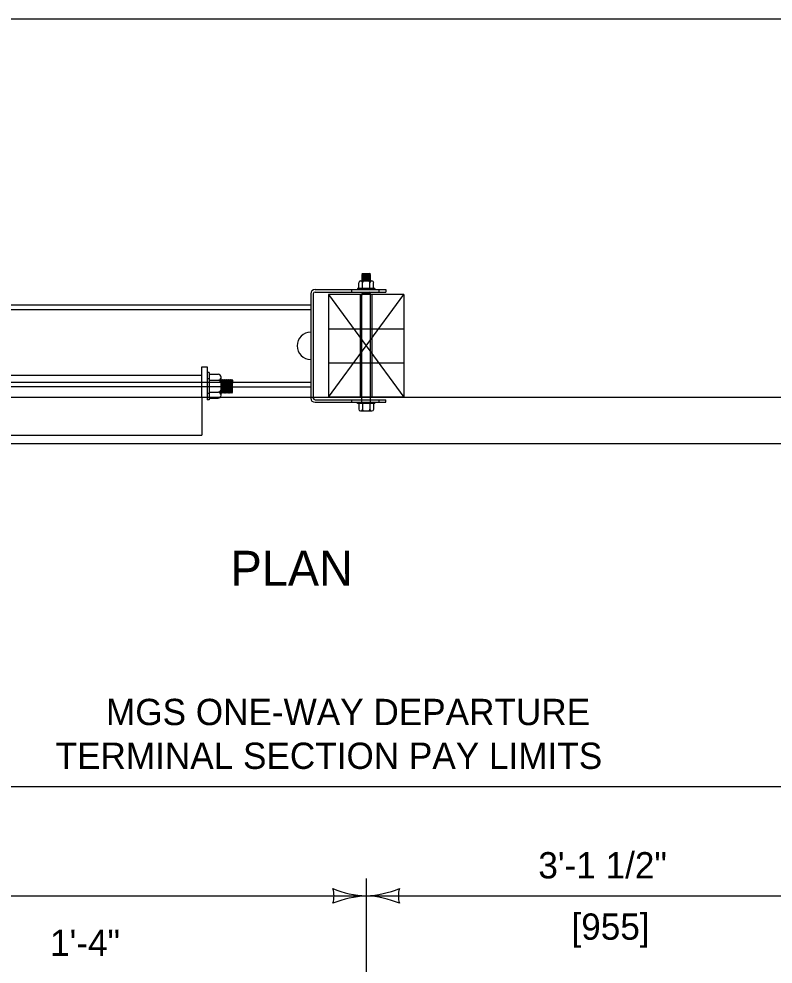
# Model space of a CAD drawing. Extents: x 49991.4 to 50021, y 49987.6 to 50011.4.
# Drawn here: x 50002.896 to 50004.618, y 49996.841 to 49998.999 of the extents above; entities that cross this region are included whole.
import ezdxf

# ---------------------------------------------------------------- set-up
doc = ezdxf.new("R2010")
doc.units = 0
for name, color, linetype in [('Level 1', 7, 'Continuous'), ('Level 2', 7, 'Continuous'), ('Level 3', 7, 'Continuous'), ('Level 4', 7, 'Continuous')]:
    doc.layers.add(name, color=color, linetype=linetype)

msp = doc.modelspace()

# ---------------------------------------------------------------- linework, layer by layer
at = {"layer": 'Level 1'}
for p, q in [((50003.6976, 49998.4176), (50003.6792, 49998.4166)), ((50003.6792, 49998.4166), (50003.6805, 49998.4176)), ((50003.6792, 49998.4166), (50003.6805, 49998.4156)), ((50003.6976, 49998.4156), (50003.6792, 49998.4147)), ((50003.6792, 49998.4147), (50003.6805, 49998.4156)), ((50003.6792, 49998.4147), (50003.6805, 49998.4137)), ((50003.6976, 49998.4137), (50003.6792, 49998.4128)), ((50003.6792, 49998.4128), (50003.6805, 49998.4137)), ((50003.6792, 49998.4128), (50003.6805, 49998.4118)), ((50003.6976, 49998.4118), (50003.6792, 49998.4109)), ((50003.6792, 49998.4109), (50003.6805, 49998.4118)), ((50003.6792, 49998.4109), (50003.6805, 49998.4099)), ((50003.6805, 49998.4176), (50003.6976, 49998.4176)), ((50003.6987, 49998.4166), (50003.6805, 49998.4156)), ((50003.6987, 49998.4147), (50003.6805, 49998.4137)), ((50003.6987, 49998.4128), (50003.6805, 49998.4118)), ((50003.6987, 49998.4109), (50003.6805, 49998.4099)), ((50003.6976, 49998.4176), (50003.6987, 49998.4166)), ((50003.6976, 49998.4156), (50003.6987, 49998.4166)), ((50003.6976, 49998.4156), (50003.6987, 49998.4147)), ((50003.6976, 49998.4137), (50003.6987, 49998.4147)), ((50003.6976, 49998.4137), (50003.6987, 49998.4128)), ((50003.6976, 49998.4118), (50003.6987, 49998.4128)), ((50003.6976, 49998.4118), (50003.6987, 49998.4109)), ((50003.6976, 49998.4099), (50003.6987, 49998.4109)), ((50003.672, 49998.384), (50003.672, 49998.3969)), ((50003.6762, 49998.401), (50003.7018, 49998.401)), ((50003.6976, 49998.4099), (50003.6792, 49998.409)), ((50003.6792, 49998.409), (50003.6805, 49998.4099)), ((50003.6792, 49998.409), (50003.6805, 49998.408)), ((50003.6976, 49998.408), (50003.6792, 49998.407)), ((50003.6792, 49998.407), (50003.6805, 49998.408)), ((50003.6792, 49998.407), (50003.6805, 49998.406)), ((50003.6976, 49998.406), (50003.6792, 49998.4051)), ((50003.6792, 49998.4051), (50003.6805, 49998.406)), ((50003.6792, 49998.4051), (50003.6805, 49998.4042)), ((50003.6976, 49998.4042), (50003.6792, 49998.4032)), ((50003.6792, 49998.4032), (50003.6805, 49998.4042)), ((50003.6792, 49998.4032), (50003.6805, 49998.4022)), ((50003.6976, 49998.4022), (50003.6792, 49998.4013)), ((50003.6792, 49998.4013), (50003.6805, 49998.4022)), ((50003.6792, 49998.4013), (50003.6796, 49998.401)), ((50003.6987, 49998.409), (50003.6805, 49998.408)), ((50003.6987, 49998.407), (50003.6805, 49998.406)), ((50003.6987, 49998.4051), (50003.6805, 49998.4042)), ((50003.6987, 49998.4032), (50003.6805, 49998.4022)), ((50003.6805, 49998.384), (50003.6805, 49998.3969)), ((50003.6987, 49998.4013), (50003.6956, 49998.401)), ((50003.6975, 49998.384), (50003.6975, 49998.3969)), ((50003.6976, 49998.4099), (50003.6987, 49998.409)), ((50003.6976, 49998.408), (50003.6987, 49998.409)), ((50003.6976, 49998.408), (50003.6987, 49998.407)), ((50003.6976, 49998.406), (50003.6987, 49998.407)), ((50003.6976, 49998.406), (50003.6987, 49998.4051)), ((50003.6976, 49998.4042), (50003.6987, 49998.4051)), ((50003.6976, 49998.4042), (50003.6987, 49998.4032)), ((50003.6976, 49998.4022), (50003.6987, 49998.4032)), ((50003.6976, 49998.4022), (50003.6987, 49998.4013)), ((50003.6984, 49998.401), (50003.6987, 49998.4013)), ((50003.706, 49998.384), (50003.706, 49998.3969)), ((50003.5623, 49998.3715), (50003.5623, 49998.1354)), ((50003.5682, 49998.3715), (50003.5682, 49998.1354)), ((50003.5721, 49998.3813), (50003.7339, 49998.3813)), ((50003.5721, 49998.3754), (50003.7339, 49998.3754)), ((50003.6032, 49998.1354), (50003.7748, 49998.3698)), ((50003.6032, 49998.3698), (50003.7748, 49998.1354)), ((50003.6032, 49998.3698), (50003.6032, 49998.1354)), ((50003.7748, 49998.3698), (50003.6032, 49998.3698)), ((50003.7085, 49998.384), (50003.6695, 49998.384)), ((50003.6695, 49998.384), (50003.6695, 49998.3813)), ((50003.6787, 49998.384), (50003.6787, 49998.3813)), ((50003.6976, 49998.3754), (50003.6792, 49998.3745)), ((50003.6792, 49998.3745), (50003.6805, 49998.3754)), ((50003.6792, 49998.3745), (50003.6805, 49998.3735)), ((50003.6976, 49998.3735), (50003.6792, 49998.3726)), ((50003.6792, 49998.3726), (50003.6805, 49998.3735)), ((50003.6792, 49998.3726), (50003.6805, 49998.3716)), ((50003.6976, 49998.3716), (50003.6792, 49998.3707)), ((50003.6792, 49998.3707), (50003.6805, 49998.3716)), ((50003.6792, 49998.3707), (50003.6804, 49998.3698)), ((50003.6805, 49998.3754), (50003.6976, 49998.3754)), ((50003.6987, 49998.3745), (50003.6805, 49998.3735)), ((50003.6987, 49998.3726), (50003.6805, 49998.3716)), ((50003.6987, 49998.3707), (50003.6821, 49998.3698)), ((50003.6976, 49998.3754), (50003.6987, 49998.3745)), ((50003.6976, 49998.3735), (50003.6987, 49998.3745)), ((50003.6976, 49998.3735), (50003.6987, 49998.3726)), ((50003.6976, 49998.3716), (50003.6987, 49998.3726)), ((50003.6976, 49998.3716), (50003.6987, 49998.3707)), ((50003.6977, 49998.3698), (50003.6987, 49998.3707)), ((50003.6994, 49998.384), (50003.6994, 49998.3813)), ((50003.7085, 49998.384), (50003.7085, 49998.3813)), ((50003.7339, 49998.3813), (50003.7339, 49998.3754)), ((50003.7748, 49998.3698), (50003.7748, 49998.1354)), ((50001.4719, 49998.3462), (50003.5623, 49998.3462)), ((50003.5623, 49998.3462), (50003.5623, 49998.2838)), ((50003.5623, 49998.2214), (50003.5623, 49998.159)), ((50003.314, 49998.1354), (50003.314, 49998.205)), ((50003.314, 49998.205), (50003.3257, 49998.205)), ((50003.3257, 49998.205), (50003.3257, 49998.1292)), ((50002.814, 49998.1861), (50003.314, 49998.1861)), ((50003.3301, 49998.1917), (50003.3257, 49998.1917)), ((50003.3301, 49998.1771), (50003.3257, 49998.1771)), ((50003.3301, 49998.1917), (50003.3301, 49998.1292)), ((50003.3301, 49998.1878), (50003.3507, 49998.1878)), ((50003.3301, 49998.1741), (50003.3507, 49998.1741)), ((50003.3574, 49998.1399), (50003.3574, 49998.181)), ((50003.3578, 49998.1761), (50003.3574, 49998.1696)), ((50003.3574, 49998.1756), (50003.3578, 49998.1761)), ((50003.3593, 49998.1741), (50003.3578, 49998.1761)), ((50003.3593, 49998.1741), (50003.3578, 49998.1448)), ((50003.3593, 49998.1741), (50003.3609, 49998.1761)), ((50003.3609, 49998.1761), (50003.3593, 49998.1468)), ((50003.3624, 49998.1741), (50003.3609, 49998.1761)), ((50003.3624, 49998.1741), (50003.3609, 49998.1448)), ((50003.3624, 49998.1741), (50003.364, 49998.1761)), ((50003.364, 49998.1761), (50003.3624, 49998.1468)), ((50003.3655, 49998.1741), (50003.364, 49998.1761)), ((50003.3655, 49998.1741), (50003.364, 49998.1448)), ((50003.3655, 49998.1741), (50003.3671, 49998.1761)), ((50003.3671, 49998.1761), (50003.3655, 49998.1468)), ((50003.3686, 49998.1741), (50003.3671, 49998.1761)), ((50003.3686, 49998.1741), (50003.3671, 49998.1448)), ((50003.3686, 49998.1741), (50003.3701, 49998.1761)), ((50003.3701, 49998.1761), (50003.3686, 49998.1468)), ((50003.3716, 49998.1741), (50003.3701, 49998.1761)), ((50003.3716, 49998.1741), (50003.3701, 49998.1448)), ((50003.3716, 49998.1741), (50003.3732, 49998.1761)), ((50003.3732, 49998.1761), (50003.3716, 49998.1468)), ((50003.3747, 49998.1741), (50003.3732, 49998.1761)), ((50003.3747, 49998.1741), (50003.3732, 49998.1448)), ((50003.3747, 49998.1741), (50003.3763, 49998.1761)), ((50003.3763, 49998.1761), (50003.3747, 49998.1468)), ((50003.3778, 49998.1741), (50003.3763, 49998.1761)), ((50003.3778, 49998.1741), (50003.3763, 49998.1448)), ((50003.3778, 49998.1741), (50003.3794, 49998.1761)), ((50003.3794, 49998.1761), (50003.3778, 49998.1468)), ((50003.3809, 49998.1741), (50003.3794, 49998.1761)), ((50003.3809, 49998.1741), (50003.3794, 49998.1448)), ((50003.3824, 49998.1761), (50003.3809, 49998.1468)), ((50003.3809, 49998.1741), (50003.3824, 49998.1761)), ((50003.3839, 49998.1741), (50003.3824, 49998.1761)), ((50003.3839, 49998.1741), (50003.3824, 49998.1448)), ((50003.3839, 49998.1468), (50003.3839, 49998.1741)), ((50003.3839, 49998.159), (50003.5623, 49998.159)), ((50001.2278, 49998.1354), (50006.4114, 49998.1354)), ((50003.3301, 49998.1438), (50003.3257, 49998.1438)), ((50003.3301, 49998.1468), (50003.3507, 49998.1468)), ((50003.3301, 49998.1331), (50003.3507, 49998.1331)), ((50003.3578, 49998.1448), (50003.3574, 49998.1453)), ((50003.3578, 49998.1448), (50003.3593, 49998.1468)), ((50003.3609, 49998.1448), (50003.3593, 49998.1468)), ((50003.3609, 49998.1448), (50003.3624, 49998.1468)), ((50003.364, 49998.1448), (50003.3624, 49998.1468)), ((50003.364, 49998.1448), (50003.3655, 49998.1468)), ((50003.3671, 49998.1448), (50003.3655, 49998.1468)), ((50003.3671, 49998.1448), (50003.3686, 49998.1468)), ((50003.3701, 49998.1448), (50003.3686, 49998.1468)), ((50003.3701, 49998.1448), (50003.3716, 49998.1468)), ((50003.3732, 49998.1448), (50003.3716, 49998.1468)), ((50003.3732, 49998.1448), (50003.3747, 49998.1468)), ((50003.3763, 49998.1448), (50003.3747, 49998.1468)), ((50003.3763, 49998.1448), (50003.3778, 49998.1468)), ((50003.3794, 49998.1448), (50003.3778, 49998.1468)), ((50003.3794, 49998.1448), (50003.3809, 49998.1468)), ((50003.3824, 49998.1448), (50003.3809, 49998.1468)), ((50003.3824, 49998.1448), (50003.3839, 49998.1468)), ((50003.7748, 49998.1354), (50003.6032, 49998.1354)), ((50003.3301, 49998.1292), (50003.3257, 49998.1292)), ((50001.5093, 49998.0301), (50006.4114, 49998.0301))]:
    msp.add_line(p, q, dxfattribs=at)
msp.add_lwpolyline([(49999.3835, 49998.9992), (50016.7501, 49998.9992), (50016.7501, 49987.7988), (49999.3835, 49987.7988)], close=True, dxfattribs=at)
for centre, radius, start, end in [((50003.6762, 49998.3968), 0.0042, 89.5221, 179.5221), ((50003.6763, 49998.3968), 0.00423, 0.896, 90.896), ((50003.6847, 49998.3968), 0.0042, 92.0518, 179.5951), ((50003.6933, 49998.3969), 0.00418, 0.0618, 87.1409), ((50003.7018, 49998.3968), 0.00426, 88.7945, 178.7945), ((50003.7019, 49998.3969), 0.00418, 0.1602, 90.1602), ((50003.5721, 49998.3715), 0.00975, 90, 180), ((50003.5721, 49998.3715), 0.0039, 90, 180), ((50003.5623, 49998.2526), 0.0312, 90, 270), ((50003.3507, 49998.181), 0.00675, 0, 90), ((50003.3507, 49998.1809), 0.00675, 270, 360), ((50003.3507, 49998.1674), 0.00675, 0, 90), ((50003.3507, 49998.1536), 0.00675, 270, 360), ((50003.3507, 49998.1401), 0.00675, 0, 90), ((50003.3507, 49998.1399), 0.00675, 270, 360)]:
    msp.add_arc(centre, radius, start, end, dxfattribs=at)
at = {"layer": 'Level 3'}
for p, q in [((50001.3465, 49997.2468), (50006.0327, 49997.2468)), ((50003.689, 49997.0368), (50003.689, 49995.9948)), ((50001.3453, 49996.9968), (50003.689, 49996.9968)), ((50003.689, 49996.9968), (50004.8609, 49996.9968))]:
    msp.add_line(p, q, dxfattribs=at)
for centre, radius, start, end in [((50003.6982, 49997.2189), 0.2223, 247.456, 267.6395), ((50003.5608, 49996.9968), 0.0548, 342.1388, 17.8612), ((50003.6775, 49997.2295), 0.233, 272.8273, 292.0772), ((50003.8172, 49996.9968), 0.0548, 162.1388, 197.8612), ((50003.7005, 49996.7641), 0.233, 92.8273, 112.0772), ((50003.6798, 49996.7747), 0.2223, 67.456, 87.6395)]:
    msp.add_arc(centre, radius, start, end, dxfattribs=at)
at = {"layer": 'Level 4'}
for p, q in [((50003.656, 49998.3754), (50003.656, 49998.3813)), ((50003.6753, 49998.3698), (50003.6753, 49998.1354)), ((50003.6792, 49998.1239), (50003.6792, 49998.3698)), ((50003.6987, 49998.1239), (50003.6987, 49998.3698)), ((50003.7026, 49998.1354), (50003.7026, 49998.3698)), ((50003.7184, 49998.3754), (50003.7184, 49998.3813)), ((50001.4719, 49998.3355), (50003.5623, 49998.3355)), ((50003.6032, 49998.2916), (50003.7748, 49998.2916)), ((50003.6032, 49998.2136), (50003.7748, 49998.2136)), ((50001.4719, 49998.1697), (50003.5623, 49998.1697)), ((50003.3839, 49998.159), (50002.6846, 49998.159)), ((50003.314, 49998.1354), (50003.314, 49998.049)), ((50003.5623, 49998.1354), (50003.5623, 49998.1336)), ((50003.5682, 49998.1336), (50003.5682, 49998.1354)), ((50003.5721, 49998.1297), (50003.7339, 49998.1297)), ((50003.656, 49998.1239), (50003.656, 49998.1297)), ((50003.7184, 49998.1239), (50003.7184, 49998.1297)), ((50003.7339, 49998.1239), (50003.7339, 49998.1297)), ((50003.5721, 49998.1239), (50003.7339, 49998.1239)), ((50003.6695, 49998.1212), (50003.6695, 49998.1239)), ((50003.7085, 49998.1212), (50003.6695, 49998.1212)), ((50003.672, 49998.1212), (50003.672, 49998.1083)), ((50003.6787, 49998.1212), (50003.6787, 49998.1239)), ((50003.6805, 49998.1212), (50003.6805, 49998.1083)), ((50003.6975, 49998.1212), (50003.6975, 49998.1083)), ((50003.6994, 49998.1212), (50003.6994, 49998.1239)), ((50003.706, 49998.1212), (50003.706, 49998.1083)), ((50003.7085, 49998.1212), (50003.7085, 49998.1239)), ((50003.6762, 49998.1042), (50003.7018, 49998.1042)), ((50002.814, 49998.049), (50003.314, 49998.049))]:
    msp.add_line(p, q, dxfattribs=at)
for centre, radius, start, end in [((50003.5721, 49998.1336), 0.00975, 180, 270), ((50003.5721, 49998.1336), 0.0039, 180, 270), ((50003.6762, 49998.1084), 0.0042, 180.4779, 270.4779), ((50003.6763, 49998.1084), 0.00423, 269.104, 359.104), ((50003.6847, 49998.1084), 0.0042, 180.4049, 267.9482), ((50003.6933, 49998.1083), 0.00418, 272.8591, 359.9382), ((50003.7018, 49998.1084), 0.00426, 181.2055, 271.2055), ((50003.7019, 49998.1083), 0.00418, 269.8398, 359.8398)]:
    msp.add_arc(centre, radius, start, end, dxfattribs=at)

# ---------------------------------------------------------------- texts
at = {"layer": 'Level 2'}
for s, height, p in [('PLAN', 0.08, (50003.3792, 49997.7048)), ('MGS ONE-WAY DEPARTURE', 0.06, (50003.0948, 49997.3868)), ('TERMINAL SECTION PAY LIMITS', 0.06, (50002.9797, 49997.2868)), ('3\'-1 1/2"', 0.06, (50004.0821, 49997.0368)), ('[955]', 0.06, (50004.1578, 49996.8968)), ('1\'-4"', 0.06, (50002.967, 49996.8596))]:
    msp.add_text(s, height=height, dxfattribs=at).set_placement(p)

doc.saveas('drawing.dxf')
